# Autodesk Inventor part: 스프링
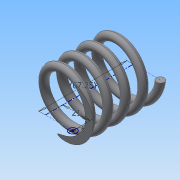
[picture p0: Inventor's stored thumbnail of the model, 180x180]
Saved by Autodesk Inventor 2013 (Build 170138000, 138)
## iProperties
Created: 2019-10
Part Number: 스프링
Material: 일반
Document SubType Name: Modeling
Designer: Administrator
Density: 1 g/cm^3
Mass: 17.498 g
Surface Area: 119.606 cm^2
Volume: 17.498 cm^3
Author: Administrator
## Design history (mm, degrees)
sketch "스케치1"
  geometry: L1 (0, 0)-(0, 67.25); L2 (0, 0)-(21, 0); L3 (0, 67.25)-(21, 67.25); C1 r 3 at (21, 0)
  constraints: 6 end point, 1 centre point, 1 coincident, 1 parallel, 1 perpendicular, 1 vertical
  dimensions: "d0" = 67.25042 distance of L1.start L1.end (derived); "d1" = 21 distance of L1.start L2.end; "d2" = 6 diameter of C1
feature "코일1" sketch "스케치1" pitch "d3" = 10; turns "d5" = 5; dims "d4" = 67.25042 (= d0), "d6" = 0, angle "d7" = 90 deg, angle "d8" = 90 deg, "d9" = 0, "d10" = 0
sketch "스케치2"
  geometry: L1 (31.074, 12.75)-(-28.926, 12.75); L2 (-28.926, 12.75)-(-28.926, 80); L3 (-28.926, 80)-(31.074, 80); L4 (31.074, 80)-(31.074, 12.75); 1 further point
  constraints: 8 end point, 2 parallel, 1 horizontal, 1 perpendicular
  dimensions: "d11" = 60 distance of L2.end L3.end; "d12" = 67.25042 distance of L1.end L2.end (= d0)
extrude "돌출1" sketch "스케치2" stored distance "d13" = 0; taper "d14" = 0 deg
node "솔리드1"
